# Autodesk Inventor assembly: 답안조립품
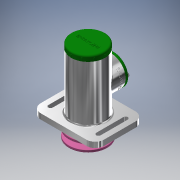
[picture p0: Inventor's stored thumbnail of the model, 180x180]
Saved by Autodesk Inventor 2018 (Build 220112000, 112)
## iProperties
Created: 2021-07
Part Number: 답안조립품
Document SubType Name: Assembly
Designer: 1class9
Author: 1class9
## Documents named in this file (19)
- C:\Users\1class9\Desktop\710706V1007\답안조립품.iam
- C:\Users\1class9\Desktop\710706V1007\본체.ipt
- C:\Users\1class9\Desktop\710706V1007\축.ipt
- C:\Users\1class9\Desktop\710706V1007\베어링 15 x 35 x 11.ipt
- C:\Users\1class9\Desktop\710706V1007\부시1.ipt
- C:\Users\1class9\Desktop\710706V1007\멈춤링 35 x 1.6.ipt
- C:\Users\1class9\Desktop\710706V1007\멈춤링 15 x 1.ipt
- C:\Users\1class9\Desktop\710706V1007\부시2.ipt
- C:\Users\1class9\Desktop\710706V1007\와셔 10 x 21.ipt
- C:\Users\1class9\Desktop\710706V1007\너트 M10.ipt
- C:\Users\1class9\Desktop\710706V1007\사이드 커버.ipt
- 사이드 커버.ipt
- C:\Users\1class9\Desktop\710706V1007\오일 실 15 25 7.ipt
- C:\Users\1class9\Desktop\710706V1007\V-벨트풀리.ipt
- C:\Users\1class9\Desktop\710706V1007\키 4 x 4 x 18.ipt
- C:\Users\1class9\Desktop\710706V1007\와셔 4 x 16.ipt
- C:\Users\1class9\Desktop\710706V1007\볼트 M4 x 10.ipt
- C:\Users\1class9\Desktop\710706V1007\탑 커버.ipt
- C:\Users\1class9\Desktop\710706V1007\와셔 3 x 6.ipt
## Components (4 placed, 2 different names)
1. V-벨트풀리:1
2. ISO 4017 M4 x 10:1
3. ISO 4017 M4 x 10:2
4. ISO 4017 M4 x 10:3
